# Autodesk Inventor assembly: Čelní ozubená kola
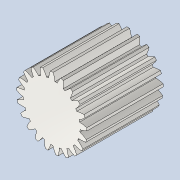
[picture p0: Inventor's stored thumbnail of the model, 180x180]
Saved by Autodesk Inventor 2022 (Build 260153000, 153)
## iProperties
ClientObjectVersion: 1
Created: 2025-05
Part Number: Čelní ozubená kola
Document SubType Name: Assembly
Designer: jbart
Categories: <?xml version="1.0" encoding="UTF-16"?> <MemberInstance><Categories><FamilyTemplate/><ParamToTemplateMap><ParamToTemplate><ParamToTemplate CategoryParameter="//
Author: jbart
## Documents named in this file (2)
- C:\Users\jbart\OneDrive\Dokumenty\Inventor\Převodovka navijáku\Satelit A\Design Accelerator\Čelní ozubená kola1.iam
- C:\Users\jbart\OneDrive\Dokumenty\Inventor\Převodovka navijáku\Satelit A\Design Accelerator\Čelní ozubené kolo11.ipt
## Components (1 placed, 1 different names)
1. Čelní ozubené kolo1:1
